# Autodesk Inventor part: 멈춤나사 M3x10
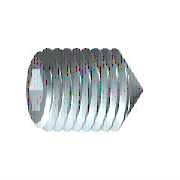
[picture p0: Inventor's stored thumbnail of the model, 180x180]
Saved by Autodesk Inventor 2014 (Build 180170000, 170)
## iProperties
Created: 2012-02
Part Number: 멈춤나사 M3x10
Material: 강철, 연강
Description: 6각 소켓 머리 없는 멈춤 나사
Document SubType Name: Modeling
Standard: KS B 1028
Designer: mduedu
Standards Organization: KS
Language: ko-KR
Size Designation: 원추점 M3x10
Categories: <MemberInstance><Categories><Category DisplayName="조임쇠" InternalName="e4da775c-781d-43d5-af7c-5136215cf5a6" Mnemonic="FSTN"><Category DisplayName="볼트" InternalN
Density: 7.86 g/cm^3
Mass: 0.471457 g
Surface Area: 1.07667 cm^2
Volume: 0.0599818 cm^3
Appearance: 강철
IsCustomPart: 1
Author: mduedu
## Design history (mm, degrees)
sketch "스케치1"
  geometry: L1 (0, 0)-(7.5, 0); L2 (10, 0.866)-(10, 1.5); L3 (10, 1.5)-(0, 1.5); L4 (10, 0.866)-(8, 0.866); L5 (8, 0.866)-(7.5, 0); L6 (0, -0.3)-(0, 1.8) reference; L7 (0, 1.5)-(0, 0)
  constraints: 13 end point, 3 parallel, 1 collinear, 1 perpendicular, 1 point on line
  dimensions: "d0" = 2 distance of L2.start L4.end (= INTI); "d1" = 60 deg angle of L5 L1; "d2" = 3 diameter of L3 L1 (= NND); "d3" = 1.73205 diameter of L4 L1 (= 1.1547 x SW); "d5" = 10 distance from line of L2 L3.end (= NLG)
revolve "본체" sketch "스케치1" stored, may be unused: angle "d6" = 90 deg
sketch "스케치2"
  geometry: L1 (-0.433, 0.75)-(0.433, 0.75); L2 (0.433, 0.75)-(0.866, 0); L3 (0.866, 0)-(0.433, -0.75); L4 (0.433, -0.75)-(-0.433, -0.75); L5 (-0.433, -0.75)-(-0.866, 0); L6 (-0.866, 0)-(-0.433, 0.75); 3 further points
  constraints: 12 end point, 1 coincident, 1 horizontal, 13 other
extrude "슬롯" join sketch "스케치2" taper "d7" = 0 deg; stored distance "d21" = 10
workaxis "Work Axis1"
workplane "Work Plane1"
sketch "스케치4"
  geometry: L1 (4.693, 1.5)-(5, 1.193) reference; L2 (5, 1.193)-(5, 0.866) reference; L3 (5, 0.866)-(3, 0.866) reference; L4 (3, 0.866)-(2.5, 0) reference; L5 (2.5, 0)-(3, -0.866) reference; L6 (3, -0.866)-(5, -0.866) reference; L7 (5, -0.866)-(5, -1.193) reference; L8 (5, -1.193)-(4.693, -1.5) reference; L9 (4.693, -1.5)-(-3.65, -1.5) reference; L10 (-3.65, -1.5)-(-5, -0.15) reference; L11 (-5, -0.15)-(-5, 0.15) reference; L12 (-5, 0.15)-(-3.65, 1.5) reference; L13 (-3.65, 1.5)-(4.693, 1.5) reference; L14 (-3.65, 1.5)-(-5.15, 0); L15 (-3.65, -1.5)-(-5.15, 0); 1 further point
  constraints: 4 end point, 2 collinear
  node "절단 모서리 투영1"
node "작업점1"
body "Solid1"
feature "스레드" dims "d12" = 10 (= NLG), "d13" = 0
chamfer "모따기1" distance "d8" = 1.35 (computed from NND, SPD, FAWI); stored, may be unused: angle "d9" = 45 deg (= FAWI), second distance "d34" = 1.35 (computed from NND, SPD, FAWI)
chamfer "모따기2" distance "d10" = 0.30673 (= -0.5 x GD1 + 0.5 x NND); stored, may be unused: angle "d11" = 45 deg (= FAWI), second distance "d35" = 0.30673 (= -0.5 x GD1 + 0.5 x NND)
other parameters: "NND" = 3 [user parameter; used in 5 equation terms], "NLG" = 10 [user parameter; used in 2 equation terms], "INTI" = 2 [user parameter; used in 1 equation term], "FAWI" = 45 deg [user parameter; used in 4 equation terms], "SW" = 1.5 [user parameter; used in 2 equation terms], "GD1" = 2.38655 (= THREADDIA - 1.2269 x PTC) [user parameter; used in 2 equation terms], "d4" = 0, "FAWI1" = 45 deg [user parameter], "SPD" = 0.3 [user parameter; used in 2 equation terms], "d36" = 0, "d37" = 0, "GUL" = 0.30673 (= 0.61345 x PTC) [user parameter], "TOA" = 30 deg [user parameter], "THREADDIA" = 3 [user parameter; used in 1 equation term], "PTC" = 0.5 [user parameter; used in 4 equation terms], "GAL" = 0.30673 (= 0.61345 x PTC) [user parameter], "E0" = 1.7325 (= 1.155 x SW) [user parameter]
